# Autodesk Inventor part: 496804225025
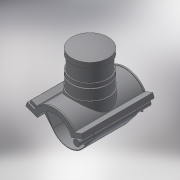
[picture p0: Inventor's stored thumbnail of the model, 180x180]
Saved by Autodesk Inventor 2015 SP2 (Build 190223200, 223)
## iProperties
Created: 2017-07
Part Number: 496804225025
Material: Generic
Description: PLASSON BALLOON SADDLE 225-2.1/2"
Document SubType Name: Modeling
Designer: KIM
Density: 1 g/cm^3
Appearance: Default
Author: KIM
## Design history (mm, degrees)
derived "496804.ipt"
feature "Solid1::496804.ipt"
feature "Solid2::496804.ipt"
tag "TaggingFeature1"
body "Solid1"
body "Solid2"
other parameters: "d0" = 225, "d1" = 258.75, "d4" = 176, "d5" = 0, "d40" = 134.55, "d96" = 263.925, "d97" = 3.52, "d98" = 0, "d120" = 100 deg, "d121" = 24.228, "d122" = 40 deg, "d123" = 517.5, "d124" = 155.25, "d126" = 0, "d143" = 231.75, "d145" = 25.96154, "d149" = 3.375, "d150" = 28.55769, "d153" = 176, "d154" = 0, "d159" = 6.75, "d161" = 3.375, "d162" = 105.6, "d163" = 0, "d164" = 112.5, "d168" = 117.61364, "d170" = 3.375, "d172" = 0, "d173" = 1, "d175" = 112.5, "d176" = 40 deg, "d177" = 18, "d180" = 0, "d185" = 57.2, "d186" = 57.2, "d187" = 129.375, "d188" = 10.125, "d190" = 0, "d191" = 207, "d193" = 6.75, "d194" = 4.4, "d195" = 90 deg, "d197" = 0, "d199" = 0, "d200" = 105, "d201" = 1, "d203" = 94.5, "d204" = 97.65, "d205" = 85.5, "d206" = 1.8, "d207" = 52.5, "d208" = 42, "d209" = 84, "d210" = 21, "d214" = 258.75, "d216" = 0, "d217" = 113.5, "d219" = 45, "d220" = 15.98, "d221" = 20 deg, "d223" = 13.94769, "d224" = 6.97385, "d226" = 0, "d227" = -17.6, "d228" = 3.375, "d229" = 49.5, "d_" = 225, "B_" = 227, "H_" = 105, "L_" = 176, "d_t" = 6, "d148" = 3.375, "d160" = 3.375, "d169" = 3.375, "d192" = 6.75, "d222" = 17.43461
